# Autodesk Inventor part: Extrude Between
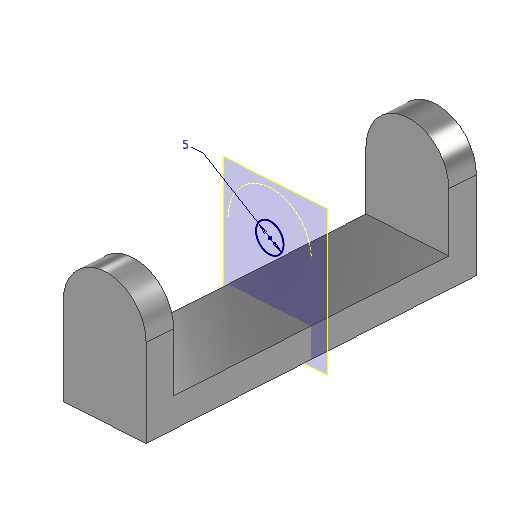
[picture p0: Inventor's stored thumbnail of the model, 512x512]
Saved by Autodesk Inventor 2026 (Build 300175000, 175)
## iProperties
Created: 2013-10
Part Number: Extrude Between
Material: Steel, Mild
Document SubType Name: Modeling
Designer: Lars Bertram Pedersen
Density: 7.85 g/cm^3
Appearance: Semi-Polished
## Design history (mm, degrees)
sketch "Sketch1"
  geometry: L1 (-7.5, 0)-(-7.5, 15); L2 (7.5, 15)-(7.5, 0); L3 (-7.5, 0)-(7.5, 0); A1 r 7.5 centre (0, 15) between (7.5, 15) and (-7.5, 15); 3 further points
  constraints: 6 end point, 2 coincident, 2 point on circle, 2 tangent, 1 centre point, 1 horizontal, 1 midpoint, 1 parallel, 1 perpendicular
  dimensions: "d6" = 15 distance of L1.start L2.end; "d7" = 15 distance from line of L3 A1.centre
extrude "Extrusion1" new body sketch "Sketch1" distance "d0" = 60; taper "d1" = 0 deg
sketch "Sketch2"
  geometry: L1 (0, 0)-(-60, 0) reference; L2 (-55, 5)-(-5, 5); L3 (-5, 5)-(-5, 22.5); L4 (-5, 22.5)-(-55, 22.5); L5 (-55, 22.5)-(-55, 5); L6 (0, 22.5)-(-60, 22.5) reference; 2 further points
  constraints: 8 end point, 2 midpoint, 2 parallel, 1 collinear, 1 horizontal, 1 perpendicular, 1 vertical alignment
  dimensions: "d2" = 5 distance between parallel lines of L2 L1; "d3" = 50 distance of L3.end L4.end
extrude "Extrusion2" cut sketch "Sketch2" extent not by distance; stored distance "d4" = 60; taper "d5" = 0 deg
workplane "Work Plane1"
body "Solid1"
sketch "Sketch3"
  geometry: C1 r 2.5 at (7.5, 10); A1 r 7.5 centre (7.5, 10) between (15, 10) and (0, 10) reference; 1 further point
  constraints: 1 centre point, 1 concentric
  dimensions: "d8" = 5 diameter of C1
